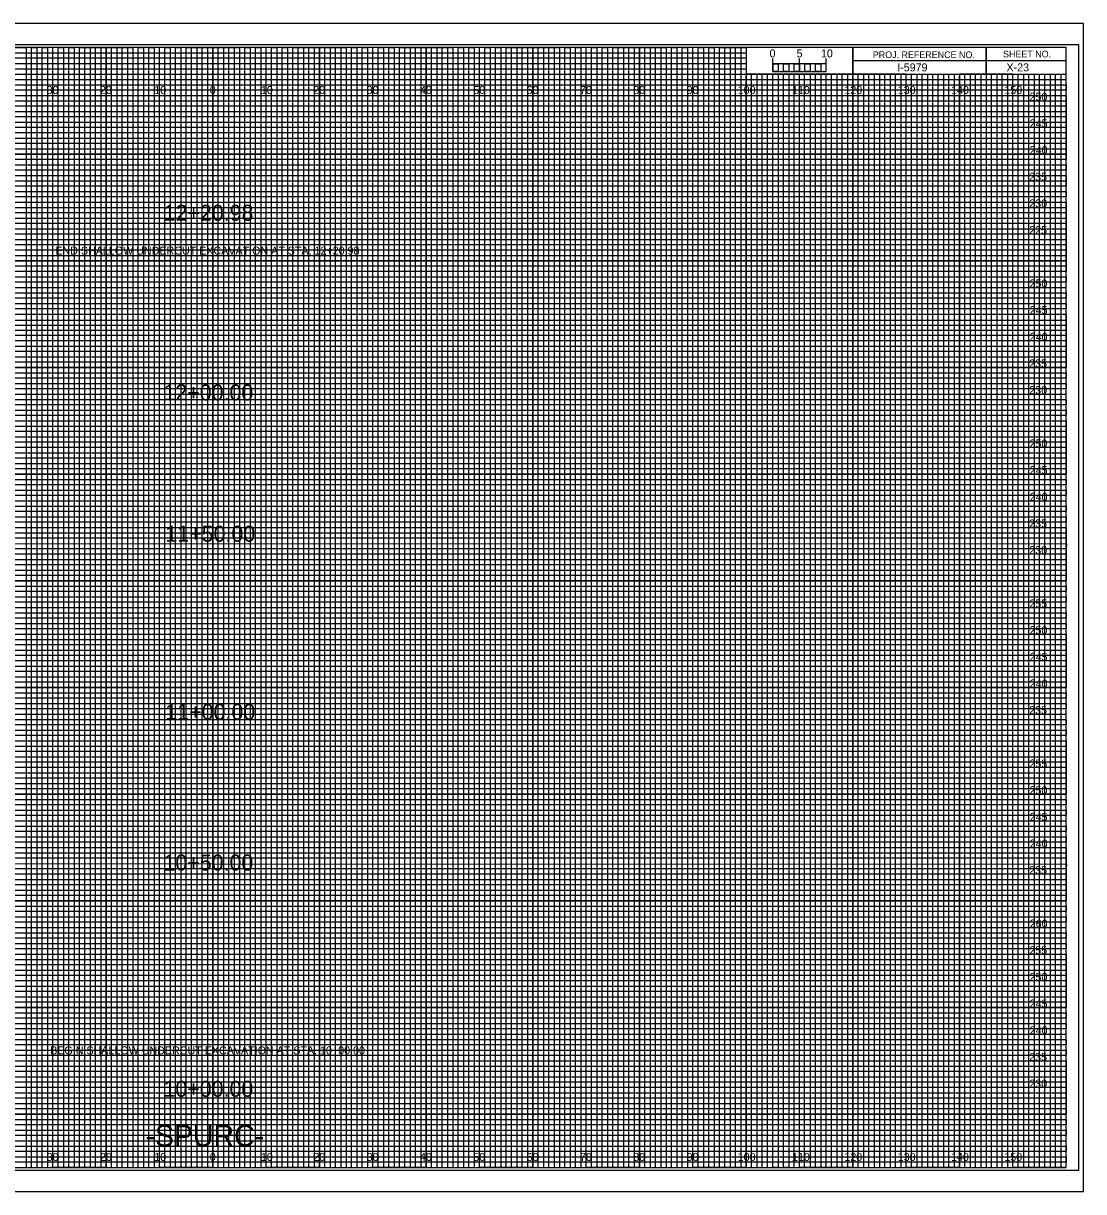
# Model space of a CAD drawing. Extents: x -13 to 323, y -5 to 215.
# Drawn here: x 124.5 to 323.3, y -4.5 to 214.5 of the extents above; entities that cross this region are included whole.
import ezdxf

# ---------------------------------------------------------------- set-up
doc = ezdxf.new("R2010")
doc.units = 0
for name, color, linetype in [('Prop XS Alignment Label', 7, 'Continuous'), ('Prop XS Bar Scale Labels', 7, 'Continuous'), ('Prop XS Elevation Labels', 7, 'Continuous'), ('Prop XS Hydro Elevations', 7, 'Continuous'), ('Prop XS Offset Labels', 7, 'Continuous'), ('Prop XS Project Number', 7, 'Continuous'), ('Prop XS Sheet Number', 7, 'Continuous'), ('Prop XS Station Labels', 7, 'Continuous'), ('Sheet Cross Section CELL', 7, 'Continuous'), ('Sheet Cross Section Grid Major CELL', 7, 'Continuous'), ('Sheet Cross Section Grid Middle CELL', 7, 'Continuous'), ('Sheet Cross Section Grid Minor 1 CELL', 7, 'Continuous'), ('Sheet Cross Section Grid Minor 2 CELL', 7, 'Continuous'), ('Sheet Cross Section Scale CELL', 7, 'Continuous'), ('Sheet Cutting Line CELL', 7, 'Continuous'), ('Sheet DOT Grid CELL', 7, 'Continuous'), ('Sheet Plot Border Inside CELL', 7, 'Continuous'), ('Sheet Plot Border Outside CELL', 7, 'Continuous')]:
    doc.layers.add(name, color=color, linetype=linetype)

msp = doc.modelspace()

# ---------------------------------------------------------------- linework, layer by layer
at = {"layer": 'Sheet Cross Section CELL'}
for p, q in [((305, 210), (305, 205)), ((305, 205), (305, 210)), ((280, 207.5), (280, 205)), ((320, 207.49), (280, 207.49)), ((280, 205), (320, 205))]:
    msp.add_line(p, q, dxfattribs=at)
for points in [[(320, 210), (0, 210), (0, 0), (320, 0)], [(280, 210), (260, 210), (260, 205.03), (280, 205.03)], [(320, 210), (280, 210), (280, 205), (320, 205)]]:
    msp.add_lwpolyline(points, close=True, dxfattribs=at)
at = {"layer": 'Sheet Cross Section Grid Major CELL'}
for p, q in [((130, 210), (120, 210)), ((130, 0), (130, 210)), ((150, 210), (140, 210)), ((140, 210), (140, 0)), ((150, 0), (150, 210)), ((170, 210), (160, 210)), ((160, 210), (160, 0)), ((170, 0), (170, 210)), ((190, 210), (180, 210)), ((180, 210), (180, 0)), ((190, 0), (190, 210)), ((210, 210), (200, 210)), ((200, 210), (200, 0)), ((210, 0), (210, 210)), ((230, 210), (220, 210)), ((220, 210), (220, 0)), ((230, 0), (230, 210)), ((250, 210), (240, 210)), ((240, 210), (240, 0)), ((250, 0), (250, 210)), ((260, 210), (260, 0)), ((270, 0), (270, 205)), ((290, 205), (280, 205)), ((280, 205), (280, 0)), ((290, 0), (290, 205)), ((310, 205), (300, 205)), ((300, 205), (300, 0)), ((310, 0), (310, 205)), ((140, 0), (130, 0)), ((160, 0), (150, 0)), ((180, 0), (170, 0)), ((200, 0), (190, 0)), ((220, 0), (210, 0)), ((240, 0), (230, 0)), ((260, 0), (250, 0)), ((280, 0), (270, 0)), ((300, 0), (290, 0)), ((320, 0), (310, 0)), ((320, 0), (320, 0))]:
    msp.add_line(p, q, dxfattribs=at)
for points in [[(0, 200), (320, 200), (320, 190), (0, 190)], [(0, 180), (320, 180), (320, 170), (0, 170)], [(0, 160), (320, 160), (320, 150), (0, 150)], [(0, 140), (320, 140), (320, 130), (0, 130)], [(0, 120), (320, 120), (320, 110), (0, 110)], [(0, 100), (320, 100), (320, 90), (0, 90)], [(0, 80), (320, 80), (320, 70), (0, 70)], [(0, 60), (320, 60), (320, 50), (0, 50)], [(0, 40), (320, 40), (320, 30), (0, 30)], [(0, 20), (320, 20), (320, 10), (0, 10)]]:
    msp.add_lwpolyline(points, dxfattribs=at)
at = {"layer": 'Sheet Cross Section Grid Middle CELL'}
for points in [[(115, 210), (125, 210), (125, 0), (135, 0), (135, 210), (145, 210), (145, 0), (155, 0), (155, 210), (165, 210), (165, 0), (175, 0), (175, 210), (185, 210), (185, 0), (195, 0), (195, 210), (205, 210), (205, 0), (215, 0), (215, 210), (225, 210), (225, 0), (235, 0), (235, 210), (245, 210), (245, 0), (255, 0), (255, 210), (259.93, 210), (260, 210), (260, 205), (264.99, 205), (264.99, 0), (275, 0), (275, 205), (285, 205), (285, 0), (295, 0), (295, 205), (305, 205), (305, 0), (315, 0), (315, 205)], [(0, 205), (275, 205)], [(0, 185), (320, 185), (320, 195), (0, 195)], [(0, 165), (320, 165), (320, 175), (0, 175)], [(0, 145), (320, 145), (320, 155), (0, 155)], [(0, 125), (320, 125), (320, 135), (0, 135)], [(0, 105), (320, 105), (320, 115), (0, 115)], [(0, 85), (320, 85), (320, 95), (0, 95)], [(0, 65), (320, 65), (320, 75), (0, 75)], [(0, 45), (320, 45), (320, 55), (0, 55)], [(0, 25), (320, 25), (320, 35), (0, 35)], [(0, 5), (320, 5), (320, 15), (0, 15)]]:
    msp.add_lwpolyline(points, dxfattribs=at)
at = {"layer": 'Sheet Cross Section Grid Minor 1 CELL'}
for p, q in [((0, 209), (260, 209)), ((260, 209), (260, 207.98)), ((260, 207.98), (0, 207.98)), ((0, 207), (260, 207)), ((260, 205.89), (0, 205.89)), ((260, 207), (260, 205.89)), ((0, 204), (320, 204))]:
    msp.add_line(p, q, dxfattribs=at)
for points in [[(0, 203), (270, 203), (320, 203), (320, 202), (0, 202)], [(0, 201), (320, 201), (320, 199), (0, 199)], [(0, 198), (320, 198), (320, 197), (0, 196.98)], [(0, 196), (320, 196), (320, 194), (0, 194)], [(0, 193), (320, 193), (320, 192), (0, 192)], [(0, 191), (320, 191), (320, 189), (0, 189)], [(0, 188), (320, 188), (320, 187), (0, 187)], [(0, 186), (320, 186), (320, 184), (0, 184)], [(0, 183), (320, 183), (320, 182), (0, 182)], [(0, 181), (320, 181), (320, 179), (0, 179)], [(0, 178), (320, 178), (320, 177), (0, 177)], [(0, 176), (320, 176), (320, 173.95), (320, 173), (320, 172), (0, 172)], [(0, 174), (320, 174), (320, 173), (0, 173)], [(0, 171), (320, 171), (320, 169), (0, 169.03)], [(0, 169.03), (320, 169), (320, 168), (0, 168)], [(0, 167), (320, 167), (320, 166), (0, 166)], [(0, 164), (320, 164), (320, 163), (0, 163)], [(0, 162), (320, 162), (320, 161), (0, 161)], [(-0.07, 158.89), (320, 158.89), (320, 157.88), (-0.07, 157.88)], [(0, 157), (320, 157), (320, 156), (0, 156)], [(0, 154), (320, 154), (320, 153), (0, 153)], [(0, 152), (320, 152), (320, 151), (0, 151)], [(0, 149), (320, 149), (320, 148), (0, 148)], [(0, 147), (320, 147), (320, 146), (0, 146)], [(0, 144), (320, 144), (320, 143), (0, 143)], [(0, 142), (320, 142), (320, 141), (0, 141)], [(0, 139), (320, 139), (319.99, 137.98), (0, 138)], [(0, 137), (320, 137), (320, 136), (0, 136)], [(0, 134), (320, 134), (320, 133), (0, 133)], [(0, 132), (320, 132), (320, 131), (0, 131)], [(0, 129), (320, 129), (320, 128), (0, 128)], [(0, 127), (320, 127), (320, 126), (0, 126)], [(0, 124), (320, 124), (320, 123), (0, 123)], [(0, 122), (320, 122), (320, 121), (0, 121)], [(0, 119), (320, 119), (320, 118), (0, 118)], [(0, 116.99), (320.07, 116.91), (320, 116), (0, 116)], [(0, 114), (320, 114), (320, 113), (0, 113)], [(0, 112), (320, 112), (320, 111), (0, 111)], [(0, 109), (320, 109), (320, 108), (0, 108)], [(0, 107), (320, 107), (320, 106), (0, 106)], [(0, 104), (320, 104), (320, 103), (0, 103)], [(0, 102), (320, 102), (320, 101), (0, 101)], [(0, 99), (320, 99), (320, 98), (0, 98)], [(0, 97), (320, 97), (320, 96), (0, 96)], [(0, 94), (320, 94), (320, 93), (0, 93)], [(0, 92), (320, 92), (320, 91), (0, 91)], [(0, 89), (320, 89), (320, 88), (0, 88)], [(0, 87), (320, 87), (320, 86), (0, 86)], [(0, 84), (320, 84), (320, 83), (0, 83)], [(0, 82), (320, 82), (320, 81), (0, 81)], [(0, 79), (320, 79), (319.99, 77.98), (0, 78)], [(0, 77), (320, 77), (320, 76), (0, 76)], [(0, 74), (320, 74), (320, 73), (0, 73)], [(0, 72), (320, 72), (320, 71), (0, 71)], [(0, 69), (320, 69), (320, 68), (0, 68)], [(0, 67), (320, 67), (320, 66), (0, 66)], [(0, 64), (320, 64), (320, 63), (0, 63)], [(0, 62), (320, 62), (320, 61), (0, 61)], [(0, 59), (320, 59), (320, 58), (0, 58)], [(0, 56.99), (320.07, 56.91), (320, 56), (0, 56)], [(0, 54), (320, 54), (320, 53), (0, 53)], [(0, 52), (320, 52), (320, 51), (0, 51)], [(0, 49), (320, 49), (320, 48), (0, 48)], [(0, 47), (320, 47), (320, 46), (0, 46)], [(0, 44), (320, 44), (320, 43), (0, 43)], [(0, 42), (320, 42), (320, 41), (0, 41)], [(0, 39), (320, 39), (320, 38), (0, 38)], [(0, 37), (320, 37), (320, 36), (0, 36)], [(0, 34), (320, 34), (320, 33), (0, 33)], [(0, 32), (320, 32), (320, 31), (0, 31)], [(0, 29), (320, 29), (320, 28), (0, 28)], [(0, 27), (320, 27), (320, 26), (0, 26)], [(0, 24), (320, 24), (320, 23), (0, 23)], [(0, 22), (320, 22), (320, 21), (0, 21)], [(0, 19), (320, 19), (320, 18), (0, 18)], [(0, 17), (320, 17), (320, 16), (0, 16)], [(0, 14), (320, 14), (320, 13), (0, 13)], [(0, 12), (320, 12), (320, 11), (0, 11)], [(0, 9), (320, 9), (320, 8), (0, 8)], [(0, 7), (320, 7), (320, 6), (0, 6)], [(0, 4), (320, 4), (320, 3), (0, 3)], [(0, 2), (320, 2), (320, 1), (0, 1)]]:
    msp.add_lwpolyline(points, dxfattribs=at)
at = {"layer": 'Sheet Cross Section Grid Minor 2 CELL'}
for p, q in [((267, 205), (266.01, 205)), ((266.01, 205), (266.01, 0)), ((267, 0), (267, 205)), ((269, 205), (268, 205)), ((268, 205), (268, 0)), ((269, 0), (269, 205)), ((266.01, 0), (265, 0)), ((268, 0), (267, 0))]:
    msp.add_line(p, q, dxfattribs=at)
for points in [[(125, 0), (126, 0), (126, 210), (127, 210), (127, 0)], [(127, 0), (128, 0), (128, 210), (129, 210), (129, 0)], [(130, 0), (131, 0), (131, 210), (132, 210), (132, 0)], [(132, 0), (133, 0), (133, 210), (134, 210), (134, 0)], [(135, 0), (136, 0), (136, 210), (137, 210), (137, 0)], [(137, 0), (138, 0), (138, 210), (139, 210), (139, 0)], [(140, 0), (141, 0), (141, 210), (142, 210), (142, 0)], [(142, 0), (143, 0), (143, 210), (144, 210), (144, 0)], [(145, 0), (146, 0), (146, 210), (147, 210), (147, 0)], [(147, 0), (148, 0), (148, 210), (149, 210), (149, 0)], [(150, 0), (151, 0), (151, 210), (152, 210), (152, 0)], [(152, 0), (153, 0), (153, 210), (154, 210), (154, 0)], [(155, 0), (156, 0), (156, 210), (157, 210), (157, 0)], [(157, 0), (158, 0), (158, 210), (159, 210), (159, 0)], [(160, 0), (161, 0), (161, 210), (162, 210), (162, 0)], [(162, 0), (163, 0), (163, 210), (164, 210), (164, 0)], [(165, 0), (166, 0), (166, 210), (167, 210), (167, 0)], [(167, 0), (168, 0), (168, 210), (169, 210), (169, 0)], [(170, 0), (171, 0), (171, 210), (172, 210), (172, 0)], [(172, 0), (173, 0), (173, 210), (174, 210), (174, 0)], [(175, 0), (176, 0), (176, 210), (177, 210), (177, 0)], [(177, 0), (178, 0), (178, 210), (179, 210), (179, 0)], [(180, 0), (181, 0), (181, 210), (182, 210), (182, 0)], [(182, 0), (183, 0), (183, 210), (184, 210), (184, 0)], [(185, 0), (186, 0), (186, 210), (187, 210), (187, 0)], [(187, 0), (188, 0), (188, 210), (189, 210), (189, 0)], [(190, 0), (191, 0), (191, 210), (192, 210), (192, 0)], [(192, 0), (193, 0), (193, 210), (194, 210), (194, 0)], [(195, 0), (196, 0), (196, 210), (197, 210), (197, 0)], [(197, 0), (198, 0), (198, 210), (199, 210), (199, 0)], [(200, 0), (201, 0), (201, 210), (202, 210), (202, 0)], [(202, 0), (203, 0), (203, 210), (204, 210), (204, 0)], [(205, 0), (206, 0), (206, 210), (207, 210), (207, 0)], [(207, 0), (208, 0), (208, 210), (209, 210), (209, 0)], [(210, 0), (211, 0), (211, 210), (212, 210), (212, 0)], [(212, 0), (213, 0), (213, 210), (214, 210), (214, 0)], [(215, 0), (216, 0), (216, 210), (217, 210), (217, 0)], [(217, 0), (218, 0), (218, 210), (219, 210), (219, 0)], [(220, 0), (221, 0), (221, 210), (222, 210), (222, 0)], [(222, 0), (223, 0), (223, 210), (224, 210), (224, 0)], [(225, 0), (226, 0), (226, 210), (227, 210), (227, 0)], [(227, 0), (228, 0), (228, 210), (229, 210), (229, 0)], [(230, 0), (231, 0), (231, 210), (232, 210), (232, 0)], [(232, 0), (233, 0), (233, 210), (234, 210), (234, 0)], [(235, 0), (236, 0), (236, 210), (237, 210), (237, 0)], [(237, 0), (238, 0), (238, 210), (239, 210), (239, 0)], [(240, 0), (241, 0), (241, 210), (242, 210), (242, 0)], [(242, 0), (243, 0), (243, 210), (244, 210), (244, 0)], [(245, 0), (246, 0), (246, 210), (247, 210), (247, 0)], [(247, 0), (248, 0), (248, 210), (249, 210), (249, 0)], [(250, 0), (251, 0), (251, 210), (252, 210), (252, 0)], [(252, 0), (253, 0), (253, 210), (254, 210), (254, 0)], [(255, 0), (256, 0), (256, 210), (257, 210), (257, 0)], [(257, 0), (258, 0), (258, 210), (259, 210), (259, 0)], [(260, 0), (261, 0), (261, 205), (262.02, 205), (262.02, 0)], [(262, 0), (263, 0), (263, 205), (263.99, 205), (263.99, 0)], [(270, 0), (270.98, 0), (270.98, 205), (272, 205), (272, 0)], [(272, 0), (273, 0), (273, 205), (274.05, 205), (274.05, 0)], [(275, 0), (276, 0), (276, 205), (277, 205), (277, 0)], [(277, 0), (278, 0), (278, 205), (279, 205), (279, 0)], [(280, 0), (281, 0), (281, 205), (282, 205), (282, 0)], [(282, 0), (283, 0), (283, 205), (284, 205), (284, 0)], [(285, 0), (286, 0), (286, 205), (287, 205), (287, 0)], [(287, 0), (288, 0), (288, 205), (289, 205), (289, 0)], [(290, 0), (291, 0), (291, 205), (292, 205), (292, 0)], [(292, 0), (293, 0), (293, 205), (294, 205), (294, 0)], [(295, 0), (296, 0), (296, 205), (297, 205), (297, 0)], [(297, 0), (298, 0), (298, 205), (299, 205), (299, 0)], [(300, 0), (301, 0), (301, 205), (302, 205), (302, 0)], [(302, 0), (303, 0), (303, 205), (304, 205), (304, 0)], [(305, 0), (306, 0), (306, 205), (307, 205), (307, 0)], [(307, 0), (308, 0), (308, 205), (309, 205), (309, 0)], [(310, 0), (311, 0), (311, 205), (312, 205), (312, 0)], [(312, 0), (313, 0), (313, 205), (314, 205), (314, 0)], [(315, 0), (316, 0), (316, 205), (317, 205), (317, 0)], [(317, 0), (318, 0), (318, 205), (319, 205), (319, 0)]]:
    msp.add_lwpolyline(points, dxfattribs=at)
at = {"layer": 'Sheet Cross Section Scale CELL'}
for p, q in [((265, 205.49), (265, 207.9)), ((265, 206.9), (265, 207.9)), ((270, 205.49), (270, 207.9)), ((275, 205.49), (275, 207.9)), ((275, 206.9), (275, 207.9))]:
    msp.add_line(p, q, dxfattribs=at)
for points in [[(275, 206.9), (265, 206.9), (265, 205.49), (275, 205.49)], [(265, 206.9), (266, 206.9), (266, 205.49), (265, 205.49)], [(267, 206.9), (268, 206.9), (268, 205.49), (267, 205.49)], [(269, 206.9), (270, 206.9), (270, 205.49), (269, 205.49)], [(271, 206.9), (272, 206.9), (272, 205.49), (271, 205.49)], [(273, 206.9), (274, 206.9), (274, 205.49), (273, 205.49)]]:
    msp.add_lwpolyline(points, close=True, dxfattribs=at)
at = {"layer": 'Sheet Cutting Line CELL'}
for p, q in [((323.3, 214.5), (-13.4, 214.5)), ((-13.4, -4.5), (323.3, -4.5))]:
    msp.add_line(p, q, dxfattribs=at)
at = {"layer": 'Sheet DOT Grid CELL'}
for p, q in [((130, 0), (130, 210)), ((140, 0), (140, 210)), ((150, 0), (150, 210)), ((160, 0), (160, 210)), ((170, 0), (170, 210)), ((180, 0), (180, 210)), ((190, 0), (190, 210)), ((200, 0), (200, 210)), ((210, 0), (210, 210)), ((220, 0), (220, 210)), ((230, 0), (230, 210)), ((240, 0), (240, 210)), ((250, 0), (250, 210)), ((260, 0), (260, 204.69)), ((270, 0), (270, 204.69)), ((280, 0), (280, 204.69)), ((290, 0), (290, 204.69)), ((300, 0), (300, 204.69)), ((310, 0), (310, 204.69)), ((0, 200), (320, 200)), ((0, 190), (320, 190)), ((0, 180), (320, 180)), ((0, 170), (320, 170)), ((0, 160), (320, 160)), ((0, 150), (320, 150)), ((0, 140), (320, 140)), ((0, 130), (320, 130)), ((0, 120), (320, 120)), ((0, 110), (320, 110)), ((0, 100), (320, 100)), ((0, 90), (320, 90)), ((0, 80), (320, 80)), ((0, 70), (320, 70)), ((0, 60), (320, 60)), ((0, 50), (320, 50)), ((0, 40), (320, 40)), ((0, 30), (320, 30)), ((0, 20), (320, 20)), ((0, 10), (320, 10))]:
    msp.add_line(p, q, dxfattribs=at)
at = {"layer": 'Sheet Plot Border Inside CELL'}
msp.add_lwpolyline([(-10.8, -0.5), (322.4, -0.5), (322.4, 210.5), (-10.8, 210.5)], close=True, dxfattribs=at)
at = {"layer": 'Sheet Plot Border Outside CELL'}
msp.add_lwpolyline([(-13.4, -4.5), (323.3, -4.5), (323.3, 214.5), (-13.4, 214.5)], close=True, dxfattribs=at)

# ---------------------------------------------------------------- texts
at = {"layer": 'Prop XS Alignment Label'}
msp.add_text('-SPURC-', height=4, dxfattribs=at).set_placement((147.38, 4))
at = {"layer": 'Prop XS Bar Scale Labels'}
for s, p in [('5', (269.47, 208.12)), ('10', (274.04, 208.12))]:
    msp.add_text(s, height=1.5, dxfattribs=at).set_placement(p)
at = {"layer": 'Prop XS Elevation Labels'}
for s, p in [('250', (313.15, 200)), ('245', (313.18, 195)), ('240', (313.19, 190)), ('235', (313.09, 185)), ('230', (313.11, 180)), ('225', (313.1, 175)), ('250', (313.15, 165)), ('245', (313.18, 160)), ('240', (313.19, 155)), ('235', (313.09, 150)), ('230', (313.11, 145)), ('250', (313.15, 135)), ('245', (313.18, 130)), ('240', (313.19, 125)), ('235', (313.09, 120)), ('230', (313.11, 115)), ('255', (313.13, 105)), ('250', (313.15, 100)), ('245', (313.18, 95)), ('240', (313.19, 90)), ('235', (313.09, 85)), ('255', (313.13, 75)), ('250', (313.15, 70)), ('245', (313.18, 65)), ('240', (313.19, 60)), ('235', (313.09, 55)), ('260', (313.19, 45)), ('255', (313.13, 40)), ('250', (313.15, 35)), ('245', (313.18, 30)), ('240', (313.19, 25)), ('235', (313.09, 20)), ('230', (313.11, 15))]:
    msp.add_text(s, height=1.5, dxfattribs=at).set_placement(p)
at = {"layer": 'Prop XS Hydro Elevations'}
msp.add_text('END SHALLOW UNDERCUT EXCAVATION AT STA. 12+20.98', height=1.5, dxfattribs=at).set_placement((130.5, 171.15))
msp.add_text('BEGIN SHALLOW UNDERCUT EXCAVATION AT STA. 10+00.00', height=1.5, rotation=360, dxfattribs=at).set_placement((129.53, 21.23))
at = {"layer": 'Prop XS Offset Labels'}
for s, p in [('30', (128.86, 201.25)), ('20', (138.86, 201.25)), ('10', (149.04, 201.25)), ('0', (159.45, 201.25)), ('0', (159.45, 201.25)), ('10', (169.04, 201.25)), ('20', (178.86, 201.25)), ('30', (188.86, 201.25)), ('40', (198.86, 201.25)), ('50', (208.86, 201.25)), ('60', (218.86, 201.25)), ('70', (228.86, 201.25)), ('80', (238.86, 201.25)), ('90', (248.86, 201.25)), ('100', (258.44, 201.25)), ('110', (268.62, 201.25)), ('120', (278.44, 201.25)), ('130', (288.44, 201.25)), ('140', (298.44, 201.25)), ('150', (308.44, 201.25)), ('30', (128.86, 1.25)), ('20', (138.86, 1.25)), ('10', (149.04, 1.25)), ('0', (159.45, 1.25)), ('0', (159.45, 1.25)), ('10', (169.04, 1.25)), ('20', (178.86, 1.25)), ('30', (188.86, 1.25)), ('40', (198.86, 1.25)), ('50', (208.86, 1.25)), ('60', (218.86, 1.25)), ('70', (228.86, 1.25)), ('80', (238.86, 1.25)), ('90', (248.86, 1.25)), ('100', (258.44, 1.25)), ('110', (268.62, 1.25)), ('120', (278.44, 1.25)), ('130', (288.44, 1.25)), ('140', (298.44, 1.25)), ('150', (308.44, 1.25))]:
    msp.add_text(s, height=1.5, dxfattribs=at).set_placement(p)
at = {"layer": 'Prop XS Project Number'}
msp.add_text('I-5979', height=1.5, dxfattribs=at).set_placement((288.34, 205.5))
at = {"layer": 'Prop XS Sheet Number'}
msp.add_text('X-23', height=1.5, dxfattribs=at).set_placement((308.83, 205.5))
at = {"layer": 'Prop XS Station Labels'}
for s, p in [('12+20.98', (150.8, 177.49)), ('12+00.00', (150.77, 143.81)), ('11+50.00', (151.13, 117.33)), ('11+00.00', (151.13, 83.94)), ('10+50.00', (150.77, 55.69)), ('10+00.00', (150.77, 13.28))]:
    msp.add_text(s, height=3, dxfattribs=at).set_placement(p)
at = {"layer": 'Sheet Cross Section CELL'}
for s, p in [('PROJ. REFERENCE NO.', (283.77, 207.99)), ('SHEET NO.', (308.19, 208.12))]:
    msp.add_text(s, height=1.25, dxfattribs=at).set_placement(p)
at = {"layer": 'Sheet Cross Section Scale CELL'}
msp.add_text('0', height=1.5, dxfattribs=at).set_placement((264.41, 208.12))

doc.saveas('drawing.dxf')
